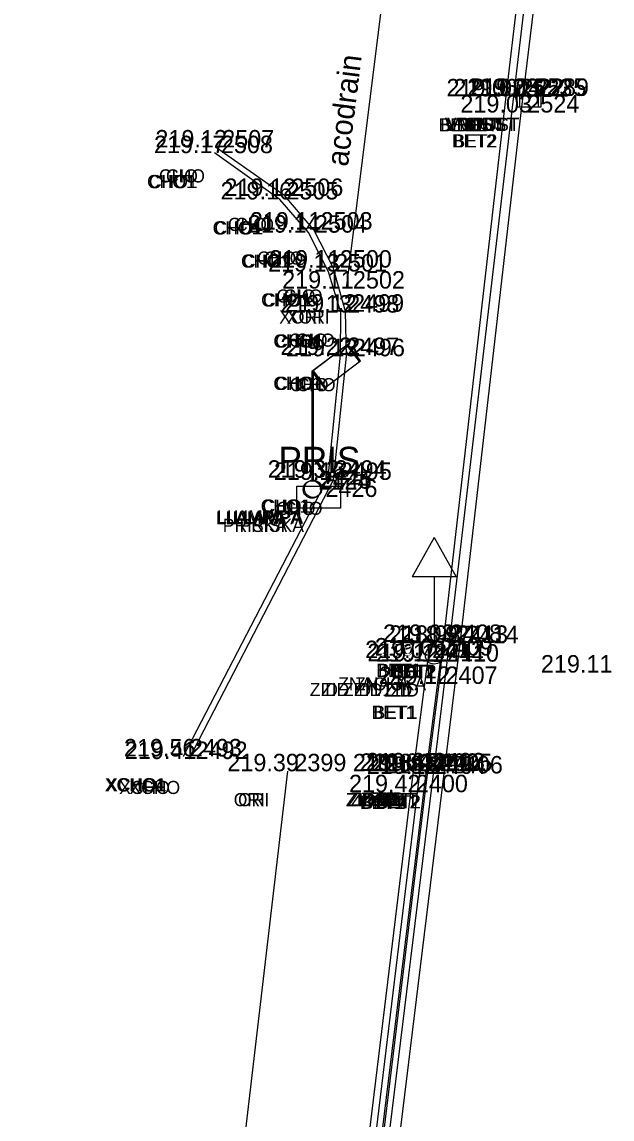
# Model space of a CAD drawing. Extents: x -471047 to -470889, y -1102859 to -1102000.
# Drawn here: x -470955.98 to -470942.48, y -1102237.69 to -1102212.58 of the extents above; entities that cross this region are included whole.
import ezdxf

# ---------------------------------------------------------------- set-up
doc = ezdxf.new("R2010")
doc.units = 0
for name, color, linetype in [('Vrstva 1', 7, 'Continuous'), ('Vrstva 19', 7, 'Continuous'), ('Vrstva 2', 7, 'Continuous'), ('Vrstva 20', 7, 'Continuous'), ('Vrstva 22', 7, 'Continuous'), ('Vrstva 23', 7, 'Continuous'), ('Vrstva 25', 7, 'Continuous'), ('Vrstva 3', 7, 'Continuous'), ('Vrstva 34', 7, 'Continuous'), ('Vrstva 35', 7, 'Continuous'), ('Vrstva 36', 7, 'Continuous'), ('Vrstva 38', 7, 'Continuous'), ('Vrstva 5', 7, 'Continuous'), ('Vrstva 7', 7, 'Continuous'), ('Vrstva 8', 7, 'Continuous')]:
    doc.layers.add(name, color=color, linetype=linetype)

msp = doc.modelspace()

# ---------------------------------------------------------------- linework, layer by layer
at = {"layer": 'Vrstva 1'}
for points in [[(-471040.344, -1102858.385), (-471031.676, -1102846.187), (-471026.357, -1102838.629), (-471023.212, -1102833.975), (-471019.21, -1102827.465), (-471016.861, -1102823.272), (-471013.099, -1102815.912), (-471010.824, -1102810.955), (-471007.329, -1102802.292), (-471005.34, -1102796.515), (-471002.842, -1102787.838), (-471001.3, -1102780.997), (-471000.19, -1102774.713), (-470999.247, -1102768.204), (-470998.794, -1102764.784), (-470997.199, -1102751.812), (-470994.899, -1102732.807), (-470992.551, -1102713.262), (-470990.326, -1102694.887), (-470988.122, -1102676.57), (-470985.812, -1102657.305), (-470983.537, -1102638.407), (-470981.386, -1102620.622), (-470979.843, -1102608.014), (-470976.377, -1102579.253), (-470972.945, -1102550.69), (-470970.475, -1102530.206), (-470967.905, -1102508.801), (-470965.053, -1102485.131), (-470962.734, -1102465.9), (-470960.173, -1102444.812), (-470957.795, -1102425.103), (-470954.965, -1102401.839), (-470953.834, -1102392.574), (-470952.33, -1102379.985), (-470950.744, -1102366.853), (-470948.978, -1102352.106), (-470947.037, -1102335.844), (-470944.949, -1102318.462), (-470944.013, -1102310.745), (-470942.39, -1102297.267), (-470939.519, -1102273.45), (-470937.593, -1102257.43), (-470936.064, -1102244.81), (-470934.114, -1102228.634), (-470931.621, -1102207.856), (-470929.536, -1102190.857), (-470926.572, -1102166.31), (-470924.91, -1102152.663), (-470923.413, -1102140.333), (-470921.923, -1102127.669), (-470921.155, -1102120.084), (-470920.446, -1102109.574), (-470919.912, -1102099.137), (-470919.63, -1102088.981), (-470919.523, -1102081.193), (-470919.563, -1102070.395), (-470919.714, -1102064.236), (-470920.134, -1102054.704), (-470920.462, -1102047.615), (-470920.599, -1102044.52), (-470920.743, -1102041.873), (-470921.125, -1102034.455), (-470921.774, -1102030.337), (-470922.418, -1102027.787), (-470923.734, -1102023.93), (-470924.872, -1102021.434), (-470926.752, -1102018.182), (-470927.953, -1102016.45), (-470929.616, -1102014.424), (-470932.252, -1102011.756), (-470935.111, -1102009.425), (-470938.391, -1102007.371), (-470942.651, -1102005.401)], [(-471041.328, -1102857.18), (-471032.144, -1102844.242), (-471027.583, -1102837.763), (-471024.388, -1102833.028), (-471020.451, -1102826.6), (-471018.089, -1102822.378), (-471014.542, -1102815.445), (-471012.233, -1102810.418), (-471009.247, -1102803.108), (-471006.795, -1102796.098), (-471004.315, -1102787.532), (-471002.782, -1102780.723), (-471001.674, -1102774.458), (-471000.75, -1102768.095), (-471000.28, -1102764.601), (-470998.692, -1102751.741), (-470996.378, -1102732.635), (-470994.028, -1102713.058), (-470991.808, -1102694.749), (-470989.616, -1102676.447), (-470987.284, -1102657.013), (-470985.031, -1102638.272), (-470982.87, -1102620.431), (-470981.334, -1102607.933), (-470977.881, -1102579.263), (-470974.429, -1102550.492), (-470971.964, -1102530.054), (-470969.391, -1102508.607), (-470966.54, -1102484.984), (-470964.231, -1102465.853), (-470961.679, -1102444.752), (-470959.304, -1102425.078), (-470956.455, -1102401.634), (-470955.339, -1102392.489), (-470953.812, -1102379.71), (-470952.249, -1102366.808), (-470950.479, -1102352.023), (-470948.536, -1102335.868), (-470946.426, -1102318.233), (-470945.493, -1102310.531), (-470943.864, -1102297.013), (-470940.984, -1102273.071), (-470939.078, -1102257.195), (-470937.559, -1102244.684), (-470935.592, -1102228.353), (-470933.101, -1102207.653), (-470931.011, -1102190.57), (-470928.046, -1102166.021), (-470926.409, -1102152.578), (-470924.898, -1102140.121), (-470923.427, -1102127.544), (-470922.647, -1102119.826), (-470921.919, -1102109.229), (-470921.42, -1102099.134), (-470921.127, -1102089.016), (-470921.023, -1102081.453), (-470921.061, -1102070.468), (-470921.209, -1102064.314), (-470921.666, -1102053.966), (-470922.156, -1102043.345), (-470922.299, -1102039.934), (-470922.637, -1102034.36), (-470923.091, -1102031.241), (-470923.847, -1102028.247), (-470925.083, -1102024.594), (-470926.222, -1102022.086), (-470928.04, -1102018.943), (-470929.138, -1102017.357), (-470930.929, -1102015.175), (-470933.062, -1102013.049), (-470936.379, -1102010.368), (-470939.169, -1102008.662), (-470942.899, -1102006.906), (-470945.661, -1102005.908)], [(-471043.557, -1102855.955), (-471035.129, -1102844.026), (-471029.872, -1102836.499), (-471026.577, -1102831.578), (-471022.675, -1102825.415), (-471020.123, -1102821.053), (-471016.667, -1102814.59), (-471014.208, -1102809.45), (-471011.177, -1102802.451), (-471008.55, -1102795.333), (-471006.082, -1102787.209), (-471004.464, -1102780.376), (-471003.265, -1102774.167), (-471002.327, -1102767.948), (-471001.636, -1102762.527), (-471000.297, -1102751.605), (-470997.959, -1102732.524), (-470995.602, -1102712.802), (-470993.412, -1102694.623), (-470991.21, -1102676.17), (-470988.891, -1102656.857), (-470986.625, -1102638.083), (-470984.455, -1102620.195), (-470982.936, -1102607.733), (-470979.497, -1102579.223), (-470976.023, -1102550.279), (-470973.554, -1102529.822), (-470970.991, -1102508.497), (-470968.146, -1102484.787), (-470965.835, -1102465.72), (-470963.284, -1102444.529), (-470960.91, -1102424.942), (-470958.043, -1102401.343), (-470956.946, -1102392.356), (-470955.396, -1102379.408), (-470953.851, -1102366.636), (-470952.049, -1102351.733), (-470950.124, -1102335.611), (-470948.034, -1102318.083), (-470947.094, -1102310.328), (-470945.421, -1102296.51), (-470942.58, -1102272.848), (-470940.675, -1102256.948), (-470939.176, -1102244.526), (-470937.187, -1102228.174), (-470934.708, -1102207.467), (-470932.621, -1102190.433), (-470929.634, -1102165.778), (-470928.004, -1102152.415), (-470926.45, -1102139.595), (-470925.003, -1102127.418), (-470924.249, -1102119.695), (-470923.515, -1102109.093), (-470923.018, -1102099.069), (-470922.711, -1102088.911), (-470922.643, -1102081.356), (-470922.797, -1102070.414), (-470923.018, -1102064.454), (-470923.52, -1102053.203), (-470923.823, -1102047.529), (-470924.123, -1102041.506), (-470924.462, -1102037.486), (-470924.934, -1102031.904), (-470925.664, -1102028.672), (-470926.771, -1102025.506), (-470927.959, -1102022.914), (-470929.674, -1102020.028), (-470930.76, -1102018.498), (-470932.447, -1102016.478), (-470935.215, -1102013.816), (-470937.644, -1102011.98), (-470940.381, -1102010.371), (-470943.968, -1102008.669), (-470947.145, -1102007.524), (-470950.874, -1102006.74)], [(-471044.756, -1102855.056), (-471036.376, -1102843.177), (-471031.167, -1102835.741), (-471027.859, -1102830.8), (-471023.934, -1102824.593), (-471021.43, -1102820.312), (-471018.011, -1102813.91), (-471015.536, -1102808.75), (-471012.578, -1102801.897), (-471009.95, -1102794.77), (-471007.561, -1102786.914), (-471005.936, -1102780.074), (-471004.727, -1102773.818), (-471003.828, -1102767.827), (-471003.121, -1102762.345), (-471001.787, -1102751.467), (-470999.446, -1102732.348), (-470997.073, -1102712.539), (-470994.902, -1102694.521), (-470992.696, -1102676.023), (-470990.376, -1102656.68), (-470988.131, -1102638.071), (-470985.947, -1102620.018), (-470984.417, -1102607.512), (-470980.993, -1102579.08), (-470977.514, -1102550.137), (-470975.048, -1102529.649), (-470972.488, -1102508.37), (-470969.618, -1102484.508), (-470967.34, -1102465.669), (-470964.767, -1102444.39), (-470962.402, -1102424.781), (-470959.534, -1102401.193), (-470958.432, -1102392.151), (-470956.883, -1102379.208), (-470955.335, -1102366.424), (-470953.535, -1102351.506), (-470951.606, -1102335.399), (-470949.519, -1102317.94), (-470948.575, -1102310.159), (-470946.889, -1102296.144), (-470944.056, -1102272.618), (-470942.139, -1102256.659), (-470940.657, -1102244.341), (-470938.638, -1102227.749), (-470936.19, -1102207.298), (-470934.102, -1102190.255), (-470931.124, -1102165.639), (-470929.492, -1102152.254), (-470927.915, -1102139.252), (-470926.46, -1102127.103), (-470925.74, -1102119.604), (-470925.012, -1102108.913), (-470924.523, -1102099.054), (-470924.217, -1102088.866), (-470924.148, -1102081.334), (-470924.301, -1102070.391), (-470924.518, -1102064.43), (-470924.97, -1102054.435), (-470925.588, -1102041.569), (-470925.963, -1102035.313), (-470926.405, -1102032.225), (-470927.078, -1102029.198), (-470928.123, -1102026.148), (-470929.318, -1102023.558), (-470930.84, -1102020.97), (-470931.868, -1102019.515), (-470933.443, -1102017.605), (-470936.26, -1102014.885), (-470938.429, -1102013.255), (-470941.213, -1102011.639), (-470944.847, -1102009.927), (-470947.723, -1102008.912), (-470951.444, -1102008.161), (-470954.511, -1102007.931), (-470957.895, -1102008.041)]]:
    msp.add_spline(points, degree=3, dxfattribs=at)
at = {"layer": 'Vrstva 19'}
for p, q in [((-470946.553, -1102224.378), (-470947.053, -1102225.278)), ((-470946.553, -1102224.378), (-470946.053, -1102225.278)), ((-470946.053, -1102225.278), (-470947.053, -1102225.278)), ((-470946.553, -1102225.278), (-470946.553, -1102226.878))]:
    msp.add_line(p, q, dxfattribs=at)
msp.add_circle((-470946.553, -1102227.078), 0.2, dxfattribs=at)
at = {"layer": 'Vrstva 2'}
msp.add_line((-470948.683, -1102244.633), (-470946.874, -1102229.715), dxfattribs=at)
at = {"layer": 'Vrstva 20'}
msp.add_line((-470951.6, -1102244.2), (-470949.9, -1102229.729), dxfattribs=at)
at = {"layer": 'Vrstva 23'}
for p, q in [((-470948.553, -1102219.974), (-470949.348, -1102220.579)), ((-470948.528, -1102219.957), (-470949.323, -1102220.562)), ((-470948.263, -1102220.352), (-470948.553, -1102219.974)), ((-470948.238, -1102220.334), (-470948.528, -1102219.957)), ((-470949.06, -1102220.956), (-470948.263, -1102220.352)), ((-470949.036, -1102220.94), (-470948.238, -1102220.334)), ((-470949.348, -1102220.579), (-470949.348, -1102223.079)), ((-470949.348, -1102220.579), (-470949.06, -1102220.956)), ((-470949.323, -1102220.562), (-470949.323, -1102223.062)), ((-470949.323, -1102220.562), (-470949.036, -1102220.94))]:
    msp.add_line(p, q, dxfattribs=at)
msp.add_lwpolyline([(-470949.694, -1102223.204), (-470948.694, -1102223.204), (-470948.694, -1102223.704), (-470949.694, -1102223.704)], close=True, dxfattribs=at)
for centre in [(-470949.348, -1102223.279), (-470949.323, -1102223.262)]:
    msp.add_circle(centre, 0.2, dxfattribs=at)
at = {"layer": 'Vrstva 25'}
for p, q in [((-470944.665, -1102214.02), (-470944.665, -1102214.52)), ((-470944.165, -1102214.02), (-470944.665, -1102214.02)), ((-470944.603, -1102214.02), (-470944.603, -1102214.52)), ((-470944.103, -1102214.02), (-470944.603, -1102214.02)), ((-470944.165, -1102214.52), (-470944.165, -1102214.02)), ((-470944.103, -1102214.52), (-470944.103, -1102214.02)), ((-470944.665, -1102214.27), (-470944.165, -1102214.27)), ((-470944.603, -1102214.27), (-470944.103, -1102214.27)), ((-470944.665, -1102214.52), (-470944.165, -1102214.52)), ((-470944.603, -1102214.52), (-470944.103, -1102214.52))]:
    msp.add_line(p, q, dxfattribs=at)
at = {"layer": 'Vrstva 3'}
for p, q in [((-470947.026, -1102229.725), (-470946.701, -1102227.207)), ((-470946.729, -1102229.713), (-470946.408, -1102227.221)), ((-470946.408, -1102227.221), (-470946.701, -1102227.207)), ((-470948.817, -1102244.484), (-470947.026, -1102229.725)), ((-470948.557, -1102244.669), (-470946.729, -1102229.713))]:
    msp.add_line(p, q, dxfattribs=at)
at = {"layer": 'Vrstva 34'}
for p, q in [((-470944.91, -1102214.28), (-470944.91, -1102214.28)), ((-470944.73, -1102214.28), (-470944.73, -1102214.28)), ((-470944.41, -1102214.27), (-470944.41, -1102214.27)), ((-470944.35, -1102214.27), (-470944.35, -1102214.27)), ((-470944.57, -1102214.65), (-470944.57, -1102214.65)), ((-470951.58, -1102215.58), (-470951.58, -1102215.58)), ((-470951.55, -1102215.45), (-470951.55, -1102215.45)), ((-470949.97, -1102216.56), (-470949.97, -1102216.56)), ((-470950.08, -1102216.64), (-470950.08, -1102216.64)), ((-470949.3, -1102217.33), (-470949.3, -1102217.33)), ((-470949.43, -1102217.4), (-470949.43, -1102217.4)), ((-470948.97, -1102218.29), (-470948.97, -1102218.29)), ((-470948.86, -1102218.2), (-470948.86, -1102218.2)), ((-470948.56, -1102218.68), (-470948.56, -1102218.68)), ((-470948.69, -1102219.23), (-470948.69, -1102219.23)), ((-470948.58, -1102219.21), (-470948.58, -1102219.21)), ((-470948.69, -1102220.2), (-470948.69, -1102220.2)), ((-470948.56, -1102220.23), (-470948.56, -1102220.23)), ((-470948.98, -1102223.01), (-470948.98, -1102223.01)), ((-470948.86, -1102223.06), (-470948.86, -1102223.06)), ((-470949.35, -1102223.28), (-470949.35, -1102223.28)), ((-470949.32, -1102223.26), (-470949.32, -1102223.26)), ((-470949.19, -1102223.45), (-470949.19, -1102223.45)), ((-470946.34, -1102226.77), (-470946.34, -1102226.77)), ((-470946.2, -1102226.79), (-470946.2, -1102226.79)), ((-470945.96, -1102226.8), (-470945.96, -1102226.8)), ((-470946.75, -1102227.14), (-470946.75, -1102227.14)), ((-470946.55, -1102227.08), (-470946.55, -1102227.08)), ((-470946.7, -1102227.21), (-470946.7, -1102227.21)), ((-470946.41, -1102227.22), (-470946.41, -1102227.22)), ((-470942.64, -1102227.47), (-470942.64, -1102227.47)), ((-470946.44, -1102227.73), (-470946.44, -1102227.73)), ((-470952.29, -1102229.39), (-470952.29, -1102229.39)), ((-470952.16, -1102229.45), (-470952.16, -1102229.45)), ((-470949.9, -1102229.73), (-470949.9, -1102229.73)), ((-470947.03, -1102229.73), (-470947.03, -1102229.73)), ((-470946.87, -1102229.72), (-470946.87, -1102229.72)), ((-470946.73, -1102229.71), (-470946.73, -1102229.71)), ((-470946.71, -1102229.79), (-470946.71, -1102229.79)), ((-470946.56, -1102229.73), (-470946.56, -1102229.73)), ((-470946.32, -1102229.78), (-470946.32, -1102229.78)), ((-470947.12, -1102230.21), (-470947.12, -1102230.21))]:
    msp.add_line(p, q, dxfattribs=at)
at = {"layer": 'Vrstva 5'}
for p, q in [((-470944.566, -1102214.653), (-470943.48, -1102205.772)), ((-470945.959, -1102226.805), (-470944.566, -1102214.653)), ((-470946.323, -1102229.78), (-470945.959, -1102226.805)), ((-470948.153, -1102244.725), (-470946.323, -1102229.78))]:
    msp.add_line(p, q, dxfattribs=at)
at = {"layer": 'Vrstva 7'}
for p, q in [((-470944.909, -1102214.277), (-470944.017, -1102206.826)), ((-470946.341, -1102226.767), (-470944.909, -1102214.277)), ((-470950.08, -1102216.64), (-470951.58, -1102215.575)), ((-470949.431, -1102217.398), (-470950.08, -1102216.64)), ((-470948.968, -1102218.293), (-470949.431, -1102217.398)), ((-470948.685, -1102219.228), (-470948.968, -1102218.293)), ((-470948.694, -1102220.203), (-470948.685, -1102219.228)), ((-470948.981, -1102223.008), (-470948.694, -1102220.203)), ((-470952.287, -1102229.386), (-470948.981, -1102223.008)), ((-470946.441, -1102227.733), (-470946.341, -1102226.767)), ((-470946.706, -1102229.793), (-470946.441, -1102227.733)), ((-470948.509, -1102244.617), (-470946.706, -1102229.793))]:
    msp.add_line(p, q, dxfattribs=at)
at = {"layer": 'Vrstva 8'}
for p, q in [((-470944.731, -1102214.277), (-470943.734, -1102205.894)), ((-470948.562, -1102218.681), (-470947.561, -1102210.708)), ((-470946.202, -1102226.795), (-470944.731, -1102214.277)), ((-470949.967, -1102216.557), (-470951.555, -1102215.446)), ((-470949.302, -1102217.334), (-470949.967, -1102216.557)), ((-470948.86, -1102218.199), (-470949.302, -1102217.334)), ((-470948.582, -1102219.206), (-470948.86, -1102218.199)), ((-470948.56, -1102220.229), (-470948.582, -1102219.206)), ((-470948.857, -1102223.057), (-470948.56, -1102220.229)), ((-470952.159, -1102229.445), (-470948.857, -1102223.057)), ((-470946.564, -1102229.727), (-470946.202, -1102226.795)), ((-470948.387, -1102244.646), (-470946.564, -1102229.727))]:
    msp.add_line(p, q, dxfattribs=at)

# ---------------------------------------------------------------- texts
at = {"layer": 'Vrstva 22'}
msp.add_text('acodrain', height=0.5, rotation=82.8361, dxfattribs=at).set_placement((-470948.528, -1102215.901))
at = {"layer": 'Vrstva 23'}
msp.add_text('PRIS', height=0.6, dxfattribs=at).set_placement((-470950.114, -1102222.902))
at = {"layer": 'Vrstva 35'}
for s, p in [('BET1', (-470946.452, -1102215.08)), ('BET1', (-470946.41, -1102215.08)), ('VPUST', (-470946.31, -1102215.07)), ('VPUST', (-470946.25, -1102215.07)), ('VPUST', (-470945.999, -1102215.07)), ('BET', (-470946.03, -1102215.08)), ('VPUST', (-470945.939, -1102215.07)), ('BET', (-470945.869, -1102215.08)), ('BET2', (-470946.145, -1102215.45)), ('BET2', (-470946.111, -1102215.45)), ('CHO1', (-470953.122, -1102216.38)), ('CHO1', (-470953.08, -1102216.38)), ('CHO', (-470952.851, -1102216.25)), ('CHO', (-470952.689, -1102216.25)), ('CHO', (-470951.271, -1102217.36)), ('CHO', (-470951.109, -1102217.36)), ('CHO1', (-470951.622, -1102217.44)), ('CHO1', (-470951.58, -1102217.44)), ('CHO', (-470950.601, -1102218.13)), ('CHO', (-470950.439, -1102218.13)), ('CHO1', (-470950.972, -1102218.2)), ('CHO1', (-470950.93, -1102218.2)), ('CHO1', (-470950.512, -1102219.09)), ('CHO1', (-470950.47, -1102219.09)), ('CHO', (-470950.161, -1102219)), ('CHO', (-470949.999, -1102219)), ('XORI', (-470950.098, -1102219.48)), ('XORI', (-470949.924, -1102219.48)), ('CHO1', (-470950.232, -1102220.03)), ('CHO1', (-470950.19, -1102220.03)), ('CHO', (-470949.881, -1102220.01)), ('CHO', (-470949.719, -1102220.01)), ('CHO1', (-470950.232, -1102221)), ('CHO1', (-470950.19, -1102221)), ('CHO', (-470949.861, -1102221.03)), ('CHO', (-470949.699, -1102221.03)), ('CHO1', (-470950.522, -1102223.81)), ('CHO1', (-470950.48, -1102223.81)), ('CHO', (-470950.161, -1102223.86)), ('CHO', (-470949.999, -1102223.86)), ('LLAMPA', (-470951.55, -1102224.08)), ('LLAMPA', (-470951.52, -1102224.06)), ('LLAMPA', (-470951.164, -1102224.08)), ('LLAMPA', (-470951.134, -1102224.06)), ('PRISKA', (-470951.39, -1102224.25)), ('PRISKA', (-470951.004, -1102224.25)), ('BET1', (-470947.882, -1102227.57)), ('BET1', (-470947.84, -1102227.57)), ('BET2', (-470947.535, -1102227.6)), ('BET2', (-470947.501, -1102227.6)), ('BET', (-470947.5, -1102227.59)), ('BET', (-470947.339, -1102227.59)), ('ZNACKA', (-470948.75, -1102227.88)), ('ZNACKA', (-470948.364, -1102227.88)), ('ZID ZID1', (-470949.4, -1102228.01)), ('ZID ZID1', (-470949.142, -1102228.01)), ('ZID', (-470947.701, -1102228.02)), ('ZID', (-470947.549, -1102228.02)), ('BET1', (-470947.982, -1102228.53)), ('BET1', (-470947.94, -1102228.53)), ('XCHO1', (-470954.09, -1102230.19)), ('XCHO1', (-470954.057, -1102230.19)), ('XCHO', (-470953.761, -1102230.25)), ('XCHO', (-470953.524, -1102230.25)), ('ORI', (-470951.138, -1102230.53)), ('ORI', (-470951.039, -1102230.53)), ('ZID1', (-470948.572, -1102230.53)), ('ZID1', (-470948.53, -1102230.53)), ('ZZAB', (-470948.459, -1102230.52)), ('ZZAB', (-470948.234, -1102230.52)), ('BET1', (-470948.252, -1102230.59)), ('BET1', (-470948.21, -1102230.59)), ('ZID', (-470948.021, -1102230.51)), ('BET2', (-470947.895, -1102230.58)), ('ZID', (-470947.869, -1102230.51)), ('BET2', (-470947.861, -1102230.58)), ('BET', (-470947.86, -1102230.53)), ('BET', (-470947.699, -1102230.53))]:
    msp.add_text(s, height=0.3, dxfattribs=at).set_placement(p)
at = {"layer": 'Vrstva 36'}
for s, p in [(' 2522', (-470944.91, -1102214.28)), (' 2523', (-470944.73, -1102214.28)), (' 2525', (-470944.41, -1102214.27)), (' 2289', (-470944.35, -1102214.27)), (' 2524', (-470944.57, -1102214.65)), (' 2507', (-470951.55, -1102215.45)), (' 2508', (-470951.58, -1102215.58)), (' 2505', (-470950.08, -1102216.64)), (' 2506', (-470949.97, -1102216.56)), (' 2504', (-470949.43, -1102217.4)), (' 2503', (-470949.3, -1102217.33)), (' 2500', (-470948.86, -1102218.2)), (' 2501', (-470948.97, -1102218.29)), (' 2502', (-470948.56, -1102218.68)), (' 2498', (-470948.69, -1102219.23)), (' 2499', (-470948.58, -1102219.21)), (' 2497', (-470948.69, -1102220.2)), (' 2496', (-470948.56, -1102220.23)), (' 2494', (-470948.98, -1102223.01)), (' 2124', (-470949.35, -1102223.28)), (' 2445', (-470949.32, -1102223.26)), (' 2495', (-470948.86, -1102223.06)), (' 2426', (-470949.19, -1102223.45)), (' 2408', (-470946.34, -1102226.77)), (' 2413', (-470946.2, -1102226.79)), (' 2414', (-470945.96, -1102226.8)), (' 2412', (-470946.75, -1102227.14)), (' 2411', (-470946.7, -1102227.21)), (' 2409', (-470946.55, -1102227.08)), (' 2410', (-470946.41, -1102227.22)), (' 2407', (-470946.44, -1102227.73)), (' 2493', (-470952.29, -1102229.39)), (' 2492', (-470952.16, -1102229.45)), (' 2399', (-470949.9, -1102229.73)), (' 2401', (-470947.03, -1102229.73)), (' 2402', (-470946.87, -1102229.72)), (' 2403', (-470946.73, -1102229.71)), (' 2404', (-470946.71, -1102229.79)), (' 2405', (-470946.56, -1102229.73)), (' 2406', (-470946.32, -1102229.78)), (' 2400', (-470947.12, -1102230.21))]:
    msp.add_text(s, height=0.4, dxfattribs=at).set_placement(p)
at = {"layer": 'Vrstva 38'}
for s, p in [('219.06 ', (-470946.27, -1102214.28)), ('219.02 ', (-470946.111, -1102214.28)), ('219.03 ', (-470945.793, -1102214.27)), ('219.04 ', (-470945.732, -1102214.27)), ('219.03 ', (-470945.953, -1102214.65)), ('219.12 ', (-470952.931, -1102215.45)), ('219.17 ', (-470952.963, -1102215.58)), ('219.16 ', (-470951.44, -1102216.64)), ('219.12 ', (-470951.351, -1102216.56)), ('219.14 ', (-470950.812, -1102217.4)), ('219.11 ', (-470950.77, -1102217.33)), ('219.11 ', (-470950.33, -1102218.2)), ('219.13 ', (-470950.353, -1102218.29)), ('219.11 ', (-470950.03, -1102218.68)), ('219.13 ', (-470950.073, -1102219.23)), ('219.12 ', (-470949.961, -1102219.21)), ('219.22 ', (-470950.071, -1102220.2)), ('219.13 ', (-470949.943, -1102220.23)), ('219.32 ', (-470950.361, -1102223.01)), ('219.16 ', (-470950.22, -1102223.06)), ('219.03 ', (-470947.723, -1102226.77)), ('218.98 ', (-470947.584, -1102226.79)), ('218.97 ', (-470947.343, -1102226.8)), ('219.07 ', (-470948.133, -1102227.14)), ('219.12 ', (-470948.081, -1102227.21)), ('219.06 ', (-470947.91, -1102227.08)), ('219.11 ', (-470947.88, -1102227.22)), ('219.11 ', (-470944.11, -1102227.47)), ('219.12 ', (-470947.821, -1102227.73)), ('219.56 ', (-470953.65, -1102229.39)), ('219.41 ', (-470953.63, -1102229.45)), ('219.39 ', (-470951.284, -1102229.73)), ('219.64 ', (-470948.412, -1102229.73)), ('219.64 ', (-470948.252, -1102229.72)), ('219.65 ', (-470948.114, -1102229.71)), ('219.12 ', (-470948.091, -1102229.79)), ('218.97 ', (-470947.943, -1102229.73)), ('218.97 ', (-470947.703, -1102229.78)), ('219.42 ', (-470948.501, -1102230.21))]:
    msp.add_text(s, height=0.4, dxfattribs=at).set_placement(p)

doc.saveas('drawing.dxf')
